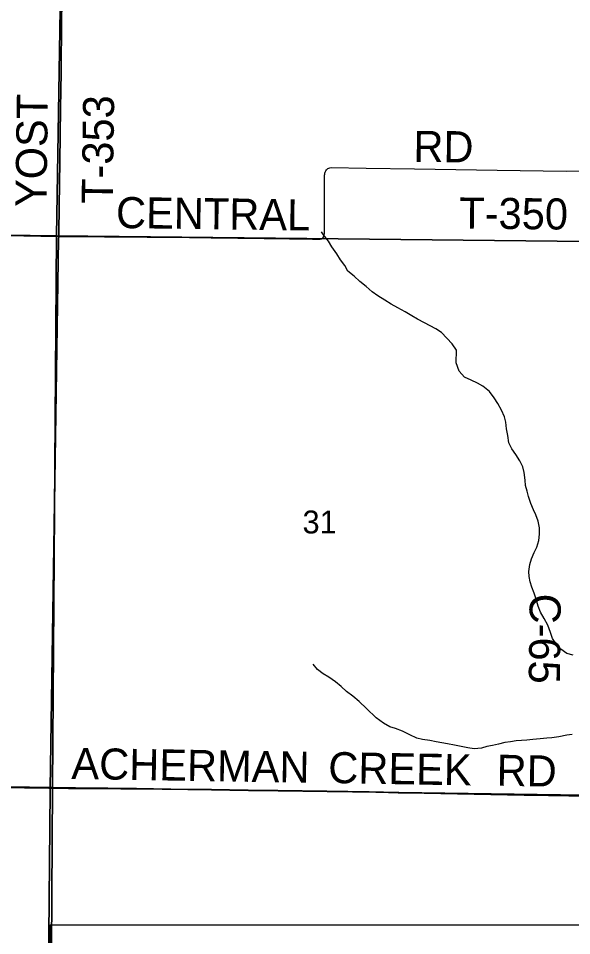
# Model space of a CAD drawing. Extents: x -8.8 to 41.4, y 0 to 34.6.
# Drawn here: x 5.315 to 6.326, y 18.372 to 20.049 of the extents above; entities that cross this region are included whole.
import ezdxf

# ---------------------------------------------------------------- set-up
doc = ezdxf.new("R2010")
doc.units = 0
for name, color, linetype in [('GM_X_Corporation', 7, 'Continuous'), ('GM_X_Minor_River', 7, 'Continuous'), ('GM_X_Section_Text', 7, 'Continuous'), ('GM_X_Township_Road', 7, 'Continuous'), ('GM_X_Township_Road_Text', 7, 'Continuous'), ('GM_X_Township_Text', 7, 'Continuous'), ('SH_Data', 7, 'Continuous')]:
    doc.layers.add(name, color=color, linetype=linetype)

msp = doc.modelspace()

# ---------------------------------------------------------------- linework, layer by layer
at = {"layer": 'GM_X_Corporation'}
for points in [[(5.4006, 20.6606), (6.3701, 20.6506), (6.3565, 19.6406), (5.3847, 19.6511), (5.4006, 20.6292)], [(4.3946, 20.6503), (5.4006, 20.6292), (5.3847, 19.6511), (4.3792, 19.6638)], [(5.3847, 19.6511), (5.3772, 18.6428), (4.3706, 18.6579), (4.3593, 18.6581), (4.3792, 19.6638)], [(6.3565, 19.6406), (6.3474, 18.629), (5.3772, 18.6428), (5.3847, 19.6511)], [(4.3706, 18.6579), (5.3772, 18.6428), (5.3707, 17.5614), (4.3651, 17.5696)]]:
    msp.add_lwpolyline(points, close=True, dxfattribs=at)
for points in [[(5.2807, 18.6436), (5.3723, 18.6421), (5.3735, 18.6421), (5.3887, 19.6449), (5.3888, 19.6506), (5.3889, 19.6562), (5.3896, 19.7052), (5.3906, 19.7872), (5.3921, 19.8841), (5.3931, 19.95), (5.3942, 20.0451), (5.3955, 20.1339)], [(5.3955, 20.1339), (5.3942, 20.0451), (5.3931, 19.95), (5.3921, 19.8841), (5.3906, 19.7872), (5.3896, 19.7052), (5.3889, 19.6562), (5.3888, 19.6506), (5.3887, 19.6449), (5.3735, 18.6421), (5.4065, 18.6419), (5.4593, 18.6417), (5.4786, 18.6416), (5.5022, 18.6414), (5.5308, 18.6412), (5.6246, 18.6396), (5.6677, 18.6391), (5.701, 18.6387), (5.7351, 18.6382), (5.7892, 18.6373), (5.8787, 18.6365), (5.9557, 18.6354), (6.0085, 18.6341), (6.0563, 18.6329), (6.239, 18.6294), (6.2831, 18.6288), (6.351, 18.628)], [(2.1, 14.1), (5.3301, 14.1), (5.3311, 14.2265), (5.3314, 14.2618), (5.3339, 14.5882), (5.3375, 15.0446), (5.3393, 15.3164), (5.3461, 16.3507), (5.3531, 16.5483), (5.3614, 17.3836), (5.3735, 18.6369), (5.3735, 18.6421), (5.3723, 18.6421), (5.2807, 18.6436)], [(6.351, 18.628), (6.2831, 18.6288), (6.239, 18.6294), (6.0563, 18.6329), (6.0085, 18.6341), (5.9557, 18.6354), (5.8787, 18.6365), (5.7892, 18.6373), (5.7351, 18.6382), (5.701, 18.6387), (5.6677, 18.6391), (5.6246, 18.6396), (5.5308, 18.6412), (5.5022, 18.6414), (5.4786, 18.6416), (5.4593, 18.6417), (5.4065, 18.6419), (5.3735, 18.6421), (5.3735, 18.6369), (5.3614, 17.3836)], [(6.3656, 17.9584), (6.3609, 17.5464), (5.3707, 17.5614), (5.3772, 18.6428), (6.3474, 18.629), (6.3731, 18.628), (6.3705, 18.3923)]]:
    msp.add_lwpolyline(points, dxfattribs=at)
at = {"layer": 'GM_X_Minor_River'}
for points in [[(6.2056, 19.3106), (6.2031, 19.3205), (6.1977, 19.3324), (6.1907, 19.3446), (6.1844, 19.3554), (6.1759, 19.3665), (6.1636, 19.3766), (6.1538, 19.3821), (6.1421, 19.3876), (6.1297, 19.3932), (6.1201, 19.404), (6.115, 19.4192), (6.1155, 19.442), (6.1073, 19.4539), (6.098, 19.4639), (6.088, 19.4743), (6.0779, 19.4814), (6.0568, 19.4924), (6.0444, 19.499), (6.0339, 19.5049), (6.0219, 19.5124), (6.0084, 19.5194), (5.9963, 19.5261), (5.9843, 19.5335), (5.972, 19.5414), (5.9615, 19.5491), (5.9506, 19.5584), (5.9391, 19.5678), (5.9282, 19.5774), (5.917, 19.5867), (5.9115, 19.5967), (5.9037, 19.6071), (5.8971, 19.6182), (5.8879, 19.6309), (5.8816, 19.6413), (5.8723, 19.6528), (5.869, 19.6586)], [(6.3283, 18.885), (6.3166, 18.8879), (6.3061, 18.8957), (6.2976, 18.9053), (6.2909, 18.9153), (6.2873, 18.9264), (6.2823, 18.9397), (6.2757, 18.952), (6.269, 18.9635), (6.2647, 18.9746), (6.2611, 18.9875), (6.2575, 18.9982), (6.2532, 19.0089), (6.2499, 19.0189), (6.2482, 19.0284), (6.2476, 19.0379), (6.2494, 19.0503), (6.2526, 19.0609), (6.2574, 19.0722), (6.2621, 19.082), (6.2658, 19.0944), (6.2671, 19.1061), (6.2669, 19.1175), (6.2645, 19.1297), (6.2605, 19.1412), (6.2558, 19.1507), (6.2511, 19.1618), (6.2471, 19.1748), (6.2443, 19.1843), (6.2414, 19.195), (6.2405, 19.2045), (6.2388, 19.2189), (6.2364, 19.2292), (6.2313, 19.2403), (6.2239, 19.2515), (6.2165, 19.2618), (6.211, 19.2729), (6.209, 19.2862), (6.2069, 19.2984), (6.2056, 19.3106)], [(6.3268, 18.7398), (6.3169, 18.7385), (6.302, 18.7357), (6.2898, 18.7341), (6.2803, 18.7331), (6.2682, 18.7318), (6.2549, 18.7305), (6.2439, 18.7296), (6.234, 18.729), (6.2245, 18.7284), (6.2138, 18.7267), (6.2036, 18.7254), (6.1921, 18.7222), (6.1811, 18.7198), (6.1708, 18.7177), (6.1613, 18.7152), (6.1476, 18.7139), (6.1358, 18.7153), (6.1241, 18.7182), (6.112, 18.7203), (6.0992, 18.7228), (6.0886, 18.7245), (6.0784, 18.7266), (6.0666, 18.7287), (6.053, 18.7305), (6.0432, 18.7333), (6.03, 18.7396), (6.0169, 18.7459), (6.0037, 18.7507), (5.9935, 18.7539), (5.9819, 18.7606), (5.9688, 18.7703), (5.9512, 18.7877), (5.9378, 18.8001), (5.9262, 18.8098), (5.9146, 18.8187), (5.9049, 18.8276), (5.8945, 18.8362), (5.8825, 18.8447), (5.8716, 18.851), (5.8615, 18.8584), (5.8533, 18.8684)]]:
    msp.add_lwpolyline(points, dxfattribs=at)
at = {"layer": 'GM_X_Township_Road'}
for points in [[(5.389, 19.65), (5.3891, 19.6556), (5.3898, 19.7047), (5.3908, 19.7867), (5.3923, 19.8836), (5.3934, 19.9494), (5.3944, 20.0446), (5.3957, 20.1334), (5.3971, 20.219), (5.3974, 20.2751), (5.3987, 20.3434), (5.3999, 20.4041), (5.4007, 20.5031), (5.4017, 20.5832), (5.4025, 20.6223), (5.4031, 20.6845), (5.4042, 20.7621), (5.4053, 20.8187), (5.4059, 20.8646), (5.4062, 20.9)], [(5.389, 19.65), (5.3978, 19.65), (5.4723, 19.6494), (5.6276, 19.6479), (5.667, 19.6473), (5.7643, 19.6461), (5.8103, 19.6459), (5.8525, 19.6452), (5.8638, 19.645), (5.8664, 19.6452), (5.8686, 19.6458), (5.8705, 19.647), (5.8719, 19.6484), (5.8728, 19.6497), (5.8733, 19.6509), (5.8736, 19.6523), (5.8739, 19.6537), (5.8741, 19.6553), (5.8742, 19.661), (5.8742, 19.6883), (5.8745, 19.7623), (5.8746, 19.7637), (5.8749, 19.7654), (5.8756, 19.7678), (5.8766, 19.77), (5.8778, 19.7718), (5.8789, 19.7731), (5.8803, 19.7742), (5.8821, 19.775), (5.8841, 19.7756), (5.8864, 19.776), (5.9504, 19.7747), (6.0387, 19.7736), (6.1897, 19.7713), (6.3158, 19.7696), (6.3529, 19.7697)], [(4.7279, 19.6552), (4.7328, 19.6567), (4.737, 19.6581), (4.7418, 19.6591), (4.7653, 19.6586), (4.8678, 19.657), (4.9517, 19.6556), (5.0387, 19.6541), (5.0996, 19.6536), (5.2039, 19.6528), (5.2872, 19.6515), (5.3251, 19.651), (5.3561, 19.6504), (5.389, 19.65)], [(4.9983, 18.6471), (5.0291, 18.6465), (5.0399, 18.6464), (5.0795, 18.6459), (5.1173, 18.6455), (5.2418, 18.6437), (5.2809, 18.6431), (5.3705, 18.6416)], [(5.3705, 18.6416), (5.3726, 18.6416), (5.3732, 18.6416)], [(5.3732, 18.6416), (5.3738, 18.6416), (5.4067, 18.6414), (5.4595, 18.6412), (5.4788, 18.6411), (5.5024, 18.6409), (5.531, 18.6406), (5.6248, 18.6391), (5.6679, 18.6386), (5.7012, 18.6381), (5.7354, 18.6377), (5.7894, 18.6367), (5.8789, 18.636), (5.9559, 18.6349), (6.0087, 18.6336), (6.0565, 18.6324), (6.2392, 18.6289), (6.2833, 18.6283), (6.3572, 18.6274)]]:
    msp.add_lwpolyline(points, dxfattribs=at)
at = {"layer": 'SH_Data'}
msp.add_lwpolyline([(5.3734, 18.3923), (7.1828, 18.3923), (7.1828, 17.9584), (5.3734, 17.9584)], close=True, dxfattribs=at)

# ---------------------------------------------------------------- texts
at = {"layer": 'GM_X_Section_Text'}
for s, rotation, p in [('YOST', 89.2115, (5.3664, 19.7034)), ('T-353', 89.1574, (5.4874, 19.7092)), ('RD', 359.5064, (6.0365, 19.7863)), ('CENTRAL', 359.2544, (5.4932, 19.6655)), ('T-350', 359.4386, (6.1203, 19.6645)), ('ACHERMAN', 359.0392, (5.4117, 18.6588)), ('CREEK', 358.988, (5.8808, 18.6513)), ('RD', 359.0118, (6.1883, 18.6463))]:
    msp.add_text(s, height=0.05682, rotation=rotation, dxfattribs=at).set_placement(p)
at = {"layer": 'GM_X_Township_Road_Text'}
msp.add_text('C-65', height=0.05682, rotation=269.3142, dxfattribs=at).set_placement((6.2492, 18.9976))
at = {"layer": 'GM_X_Township_Text'}
msp.add_text('31', height=0.04186, rotation=0, dxfattribs=at).set_placement((5.8342, 19.1073))

doc.saveas('drawing.dxf')
